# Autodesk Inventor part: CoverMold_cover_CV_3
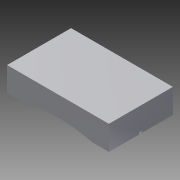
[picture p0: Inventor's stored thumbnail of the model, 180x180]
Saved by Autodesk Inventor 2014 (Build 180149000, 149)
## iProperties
Created: 2009-12
Part Number: CoverMold_cover_CV_3
Document SubType Name: Modeling
Designer: gaom
Density: 1 g/cm^3
Material: Generic
Appearance: Default
Author: gaom
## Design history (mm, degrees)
node "CoverMold_cover_CV_Base"
feature "Solid1::CoverMold_cover_CV_Base"
tag "TaggingFeature1"
body "Solid1"
